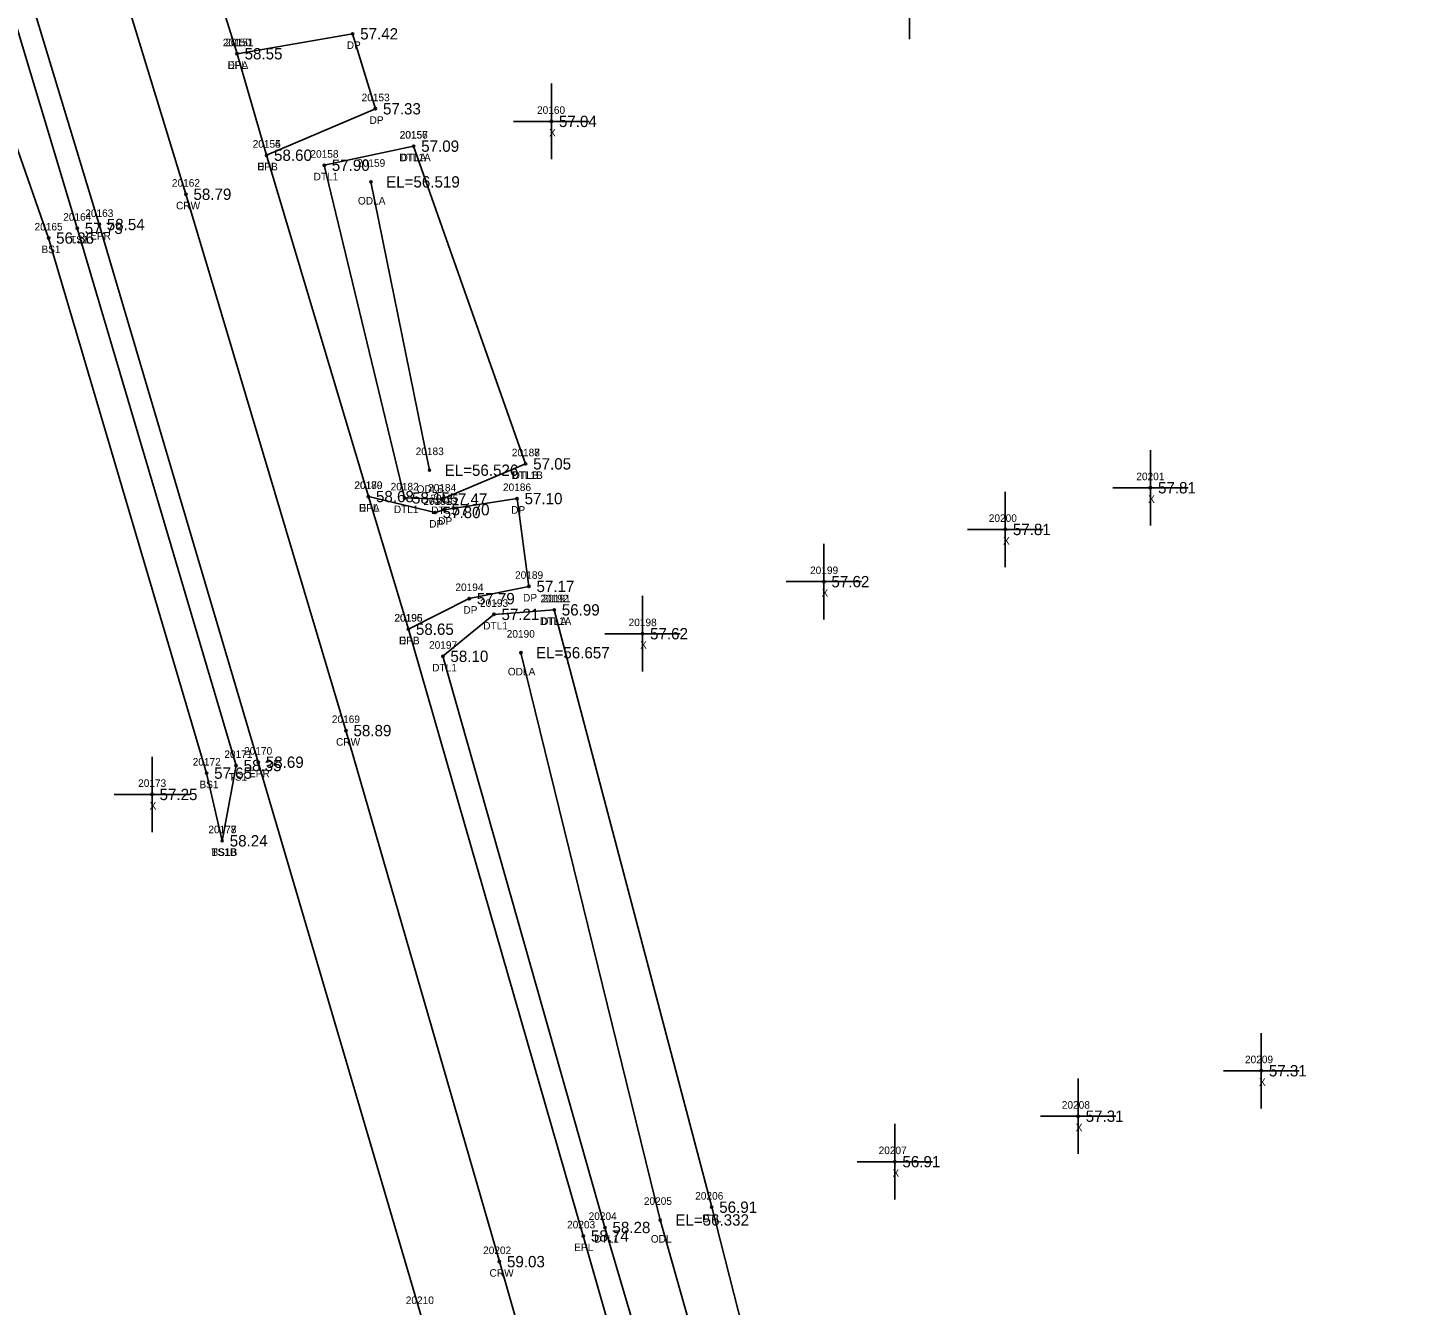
# Model space of a CAD drawing. Extents: x 2396547 to 2397655, y 770185 to 772649.
# Drawn here: x 2396876.7 to 2397062.1, y 771812.6 to 771981.7 of the extents above; entities that cross this region are included whole.
import ezdxf

# ---------------------------------------------------------------- set-up
doc = ezdxf.new("R2010")
doc.units = 0
for name, color, linetype in [('RD_DTM_BkLn1', 7, 'Continuous'), ('RD_DTM_BkLn2', 7, 'Continuous'), ('RD_DTM_BkLn_txCode', 7, 'Continuous'), ('RD_EX_Driveway', 7, 'Continuous'), ('RD_EX_Driveway_txCode', 7, 'Continuous'), ('RD_EX_H2O', 7, 'Continuous'), ('RD_EX_H2O_txCode', 7, 'Continuous'), ('RD_EX_Misc', 7, 'Continuous'), ('RD_EX_Misc_txCode', 7, 'Continuous'), ('RD_EX_Road', 7, 'Continuous'), ('RD_EX_Road_txCode', 7, 'Continuous'), ('RD_EX_TX_Driveway_ELEV', 7, 'Continuous'), ('RD_EX_TX_H2O_ELEV', 7, 'Continuous'), ('RD_EX_TX_Misc_ELEV', 7, 'Continuous'), ('RD_EX_TX_Road_ELEV', 7, 'Continuous'), ('RD_HC_Survey_ELEV', 7, 'Continuous'), ('RD_HC_Survey_txCode', 7, 'Continuous'), ('RD_SMD_Locator', 7, 'Continuous')]:
    doc.layers.add(name, color=color, linetype=linetype)

msp = doc.modelspace()

# ---------------------------------------------------------------- linework, layer by layer
at = {"layer": 'RD_DTM_BkLn1'}
msp.add_lwpolyline([(2396669.86, 772614.94), (2396704.28, 772521.49), (2396739.29, 772426.89), (2396775.36, 772328.69), (2396800.21, 772259.35), (2396825.58, 772185.8), (2396852.46, 772104.52), (2396872.48, 772041.55), (2396897.57, 771959.72), (2396918.76, 771888.68), (2396939.09, 771818.34), (2396959.29, 771747.62), (2396993.72, 771617.68), (2397022.56, 771506.67), (2397049.1, 771404.69)], dxfattribs=at)
at = {"layer": 'RD_DTM_BkLn2'}
for points in [[(2396786.67, 772254.3), (2396812.18, 772180.2), (2396838.8, 772099.9), (2396858.54, 772037.17), (2396883.18, 771955.21), (2396904.21, 771884.05), (2396902.37, 771874.08)], [(2396781.71, 772252.52), (2396807.28, 772178.23), (2396832.42, 772097.31), (2396850.69, 772038.97), (2396852.44, 772035.31), (2396852.26, 772031.59), (2396879.38, 771953.92), (2396900.31, 771883.04), (2396902.37, 771874.08)]]:
    msp.add_lwpolyline(points, dxfattribs=at)
at = {"layer": 'RD_EX_Driveway'}
for points in [[(2396904.34, 771978.33), (2396919.65, 771980.97), (2396922.67, 771971.04), (2396908.24, 771964.89)], [(2396921.74, 771919.68), (2396930.57, 771917.57), (2396931.76, 771917.94), (2396941.42, 771919.41), (2396943, 771907.78), (2396935.1, 771906.16), (2396927.03, 771902.11)]]:
    msp.add_lwpolyline(points, dxfattribs=at)
at = {"layer": 'RD_EX_H2O'}
for p, q in [((2396927.73, 771966.09), (2396942.56, 771924.01)), ((2396922.08, 771961.36), (2396929.83, 771923.17))]:
    msp.add_line(p, q, dxfattribs=at)
for points in [[(2396927.73, 771966.09), (2396915.89, 771963.56), (2396926.52, 771919.49), (2396931.47, 771919.35), (2396942.56, 771924.01)], [(2396946.35, 771904.67), (2396938.36, 771904.07), (2396931.6, 771898.52), (2396953.06, 771822.86), (2396974.04, 771751.81), (2396987.33, 771718.09)], [(2396946.35, 771904.67), (2396967.2, 771825.55), (2396985.22, 771754.85), (2396997.16, 771723.28), (2396993.62, 771717.84), (2396987.33, 771718.09)], [(2396941.93, 771898.99), (2396960.38, 771823.86), (2396980.31, 771753.37), (2396992.79, 771723.07)]]:
    msp.add_lwpolyline(points, dxfattribs=at)
at = {"layer": 'RD_EX_Misc'}
for p, q in [((2396993.38, 771980.25), (2396993.38, 771990.25)), ((2396945.97, 771964.37), (2396945.97, 771974.37)), ((2396940.97, 771969.37), (2396950.97, 771969.37)), ((2397025.31, 771915.84), (2397025.31, 771925.84)), ((2397006.09, 771910.32), (2397006.09, 771920.32)), ((2397020.31, 771920.84), (2397030.31, 771920.84)), ((2397001.09, 771915.32), (2397011.09, 771915.32)), ((2396982.06, 771903.41), (2396982.06, 771913.41)), ((2396977.06, 771908.41), (2396987.06, 771908.41)), ((2396958.04, 771896.51), (2396958.04, 771906.51)), ((2396953.04, 771901.51), (2396963.04, 771901.51)), ((2396893.08, 771875.22), (2396893.08, 771885.22)), ((2396888.08, 771880.22), (2396898.08, 771880.22)), ((2397039.99, 771838.62), (2397039.99, 771848.62)), ((2397034.99, 771843.62), (2397044.99, 771843.62)), ((2397015.73, 771832.6), (2397015.73, 771842.6)), ((2397010.73, 771837.6), (2397020.73, 771837.6)), ((2396991.46, 771826.58), (2396991.46, 771836.58)), ((2396986.46, 771831.58), (2396996.46, 771831.58))]:
    msp.add_line(p, q, dxfattribs=at)
at = {"layer": 'RD_EX_Road'}
for points in [[(2396680.92, 772617.84), (2396715.6, 772525.73), (2396750.68, 772430.62), (2396786.3, 772332.21), (2396811.38, 772263.31), (2396839.69, 772181.74), (2396863.75, 772109.83), (2396883.63, 772046.56), (2396889.54, 772027.11), (2396896.25, 772004.37), (2396904.34, 771978.33), (2396908.24, 771964.89), (2396921.74, 771919.68), (2396927.03, 771902.11), (2396950.2, 771821.74), (2396970.47, 771750.68), (2396978.33, 771721.29), (2396990.58, 771675.04), (2397004.94, 771620.49), (2397034.26, 771508.8), (2397061.11, 771410.49), (2397060.64, 771407.04), (2397062.07, 771407.67)], [(2396658.78, 772611.07), (2396693.37, 772516.9), (2396729.65, 772418.78), (2396760.7, 772333.11), (2396788.58, 772254.87), (2396814.65, 772181.57), (2396841.1, 772100.86), (2396861.19, 772037.76), (2396886.09, 771955.71), (2396907.15, 771884.49), (2396928.56, 771811.72), (2396947.65, 771744.09), (2396985.17, 771602.64), (2397011.11, 771504.04), (2397037.95, 771404.25), (2397039, 771401.22)]]:
    msp.add_lwpolyline(points, dxfattribs=at)
at = {"layer": 'RD_SMD_Locator'}
for centre in [(2396919.65, 771980.97), (2396904.34, 771978.33), (2396904.34, 771978.33), (2396922.67, 771971.04), (2396945.97, 771969.37), (2396927.73, 771966.09), (2396927.73, 771966.09), (2396908.24, 771964.89), (2396908.24, 771964.89), (2396915.89, 771963.56), (2396922.08, 771961.36), (2396897.57, 771959.72), (2396883.18, 771955.21), (2396886.09, 771955.71), (2396879.38, 771953.92), (2396929.83, 771923.17), (2396942.56, 771924.01), (2396942.56, 771924.01), (2397025.31, 771920.84), (2396921.74, 771919.68), (2396921.74, 771919.68), (2396926.52, 771919.49), (2396931.47, 771919.35), (2396941.42, 771919.41), (2396930.57, 771917.57), (2396931.76, 771917.94), (2397006.09, 771915.32), (2396982.06, 771908.41), (2396935.1, 771906.16), (2396943, 771907.78), (2396946.35, 771904.67), (2396946.35, 771904.67), (2396938.36, 771904.07), (2396927.03, 771902.11), (2396927.03, 771902.11), (2396958.04, 771901.51), (2396941.93, 771898.99), (2396931.6, 771898.52), (2396918.76, 771888.68), (2396904.21, 771884.05), (2396907.15, 771884.49), (2396900.31, 771883.04), (2396893.08, 771880.22), (2396902.37, 771874.08), (2396902.37, 771874.08), (2397039.99, 771843.62), (2397015.73, 771837.6), (2396991.46, 771831.58), (2396967.2, 771825.55), (2396953.06, 771822.86), (2396960.38, 771823.86), (2396950.2, 771821.74), (2396939.09, 771818.34)]:
    msp.add_circle(centre, 0.15, dxfattribs=at)

# ---------------------------------------------------------------- texts
at = {"layer": 'RD_DTM_BkLn_txCode'}
for s, p in [('20164', (2396881.32, 771956.21)), ('20165', (2396877.52, 771954.92)), ('BS1', (2396878.43, 771951.92)), ('TS1', (2396882.22, 771953.21)), ('20171', (2396902.66, 771885.05)), ('20172', (2396898.47, 771884.04)), ('BS1', (2396899.36, 771881.04)), ('TS1', (2396903.25, 771882.05)), ('20177', (2396900.54, 771875.08)), ('20178', (2396900.54, 771875.08)), ('TS1B', (2396900.94, 771872.08)), ('BS1B', (2396900.96, 771872.08))]:
    msp.add_text(s, height=1, dxfattribs=at).set_placement(p)
at = {"layer": 'RD_EX_Driveway_txCode'}
for s, p in [('20151', (2396902.79, 771979.33)), ('DP', (2396918.87, 771978.97)), ('DPA', (2396903.07, 771976.33)), ('20153', (2396920.84, 771972.04)), ('DP', (2396921.89, 771969.04)), ('20154', (2396906.41, 771965.89)), ('DPB', (2396906.99, 771962.89)), ('20180', (2396919.87, 771920.68)), ('20186', (2396939.56, 771920.41)), ('20181', (2396929.02, 771918.57)), ('20185', (2396929.93, 771918.94)), ('DPA', (2396920.47, 771917.68)), ('DP', (2396940.64, 771917.41)), ('DP', (2396929.79, 771915.57)), ('DP', (2396930.98, 771915.94)), ('20194', (2396933.26, 771907.16)), ('20189', (2396941.16, 771908.78)), ('DP', (2396942.22, 771905.78)), ('DP', (2396934.32, 771904.16)), ('20195', (2396925.2, 771903.11)), ('DPB', (2396925.78, 771900.11))]:
    msp.add_text(s, height=1, dxfattribs=at).set_placement(p)
at = {"layer": 'RD_EX_H2O_txCode'}
for s, p in [('20156', (2396925.87, 771967.09)), ('20157', (2396925.9, 771967.09)), ('20158', (2396914.06, 771964.56)), ('20159', (2396920.25, 771963.36)), ('DTL1A', (2396925.83, 771964.09)), ('DTLA', (2396926, 771964.09)), ('DTL1', (2396914.48, 771961.56)), ('ODLA', (2396920.35, 771958.36)), ('20183', (2396928, 771925.17)), ('20187', (2396940.73, 771925.01)), ('20188', (2396940.73, 771925.01)), ('DTL1B', (2396940.68, 771922.01)), ('DTLB', (2396940.84, 771922.01)), ('20182', (2396924.68, 771920.49)), ('ODLB', (2396928.12, 771920.17)), ('20184', (2396929.64, 771920.35)), ('DTL1', (2396925.11, 771917.49)), ('DTL1', (2396930.06, 771917.35)), ('20192', (2396944.52, 771905.67)), ('20191', (2396944.8, 771905.67)), ('20193', (2396936.52, 771905.07)), ('DTL1', (2396936.95, 771902.07)), ('DTL1A', (2396944.45, 771902.67)), ('DTLA', (2396944.62, 771902.67)), ('20190', (2396940.06, 771900.99)), ('20197', (2396929.77, 771899.52)), ('DTL1', (2396930.19, 771896.52)), ('ODLA', (2396940.2, 771895.99)), ('20205', (2396958.22, 771825.86)), ('20206', (2396965.02, 771826.55)), ('20204', (2396950.9, 771823.86)), ('DTL', (2396965.96, 771823.55)), ('DTL1', (2396951.65, 771820.86)), ('ODL', (2396959.14, 771820.86))]:
    msp.add_text(s, height=1, dxfattribs=at).set_placement(p)
at = {"layer": 'RD_EX_Misc_txCode'}
for s, p in [('20160', (2396944.07, 771970.37)), ('X', (2396945.66, 771967.37)), ('20201', (2397023.44, 771921.84)), ('X', (2397025, 771918.84)), ('20200', (2397003.9, 771916.32)), ('X', (2397005.78, 771913.32)), ('20199', (2396980.23, 771909.41)), ('X', (2396981.75, 771906.41)), ('20198', (2396956.2, 771902.51)), ('X', (2396957.72, 771899.51)), ('20173', (2396891.24, 771881.22)), ('X', (2396892.76, 771878.22)), ('20209', (2397037.83, 771844.62)), ('X', (2397039.68, 771841.62)), ('20208', (2397013.57, 771838.6)), ('X', (2397015.41, 771835.6)), ('20207', (2396989.31, 771832.58)), ('X', (2396991.15, 771829.58))]:
    msp.add_text(s, height=1, dxfattribs=at).set_placement(p)
at = {"layer": 'RD_EX_Road_txCode'}
for s, p in [('20150', (2396902.46, 771979.33)), ('EPL', (2396903.13, 771976.33)), ('20155', (2396906.41, 771965.89)), ('EPL', (2396907.04, 771962.89)), ('20163', (2396884.24, 771956.71)), ('EPR', (2396884.87, 771953.71)), ('20179', (2396919.9, 771920.68)), ('EPL', (2396920.53, 771917.68)), ('20196', (2396925.17, 771903.11)), ('EPL', (2396925.83, 771900.11)), ('20170', (2396905.28, 771885.49)), ('EPR', (2396905.92, 771882.49)), ('20203', (2396948.05, 771822.74)), ('EPL', (2396949, 771819.74)), ('20210', (2396926.69, 771812.72))]:
    msp.add_text(s, height=1, dxfattribs=at).set_placement(p)
at = {"layer": 'RD_EX_TX_Driveway_ELEV'}
for s, p in [('57.42', (2396920.65, 771980.22)), ('58.55', (2396905.34, 771977.58)), ('57.33', (2396923.67, 771970.29)), ('58.60', (2396909.24, 771964.14)), ('58.68', (2396922.74, 771918.93)), ('57.10', (2396942.42, 771918.66)), ('57.80', (2396931.57, 771916.82)), ('57.70', (2396932.76, 771917.19)), ('57.17', (2396944, 771907.03)), ('57.79', (2396936.1, 771905.41)), ('58.65', (2396928.03, 771901.36))]:
    msp.add_text(s, height=1.5, dxfattribs=at).set_placement(p)
at = {"layer": 'RD_EX_TX_H2O_ELEV'}
for s, p in [('57.09', (2396928.73, 771965.34)), ('57.09', (2396928.73, 771965.34)), ('57.90', (2396916.89, 771962.81)), ('EL=56.519', (2396924.08, 771960.61)), ('57.05', (2396943.56, 771923.26)), ('57.05', (2396943.56, 771923.26)), ('EL=56.526', (2396931.83, 771922.42)), ('58.15', (2396927.52, 771918.74)), ('57.47', (2396932.47, 771918.6)), ('57.21', (2396939.36, 771903.32)), ('56.99', (2396947.35, 771903.92)), ('56.99', (2396947.35, 771903.92)), ('58.10', (2396932.6, 771897.77)), ('EL=56.657', (2396943.93, 771898.24)), ('EL=56.332', (2396962.38, 771823.11)), ('56.91', (2396968.2, 771824.8)), ('58.28', (2396954.06, 771822.11))]:
    msp.add_text(s, height=1.5, dxfattribs=at).set_placement(p)
at = {"layer": 'RD_EX_TX_Misc_ELEV'}
for s, p in [('57.04', (2396946.97, 771968.62)), ('56.36', (2396880.38, 771953.17)), ('57.73', (2396884.18, 771954.46)), ('57.81', (2397026.31, 771920.09)), ('57.81', (2397007.09, 771914.57)), ('57.62', (2396983.06, 771907.66)), ('57.62', (2396959.04, 771900.76)), ('58.35', (2396905.21, 771883.3)), ('57.65', (2396901.31, 771882.29)), ('57.25', (2396894.08, 771879.47)), ('58.24', (2396903.37, 771873.33)), ('58.24', (2396903.37, 771873.33)), ('57.31', (2397040.99, 771842.87)), ('57.31', (2397016.73, 771836.85)), ('56.91', (2396992.46, 771830.83))]:
    msp.add_text(s, height=1.5, dxfattribs=at).set_placement(p)
at = {"layer": 'RD_EX_TX_Road_ELEV'}
for s, p in [('58.55', (2396905.34, 771977.58)), ('58.60', (2396909.24, 771964.14)), ('58.54', (2396887.09, 771954.96)), ('58.68', (2396922.74, 771918.93)), ('58.65', (2396928.03, 771901.36)), ('58.69', (2396908.15, 771883.74)), ('58.74', (2396951.2, 771820.99))]:
    msp.add_text(s, height=1.5, dxfattribs=at).set_placement(p)
at = {"layer": 'RD_HC_Survey_ELEV'}
for s, p in [('58.79', (2396898.57, 771958.97)), ('58.89', (2396919.76, 771887.93)), ('59.03', (2396940.09, 771817.59))]:
    msp.add_text(s, height=1.5, dxfattribs=at).set_placement(p)
at = {"layer": 'RD_HC_Survey_txCode'}
for s, p in [('20162', (2396895.71, 771960.72)), ('CRW', (2396896.26, 771957.72)), ('20169', (2396916.9, 771889.68)), ('CRW', (2396917.45, 771886.68)), ('20202', (2396936.93, 771819.34)), ('CRW', (2396937.78, 771816.34))]:
    msp.add_text(s, height=1, dxfattribs=at).set_placement(p)

doc.saveas('drawing.dxf')
